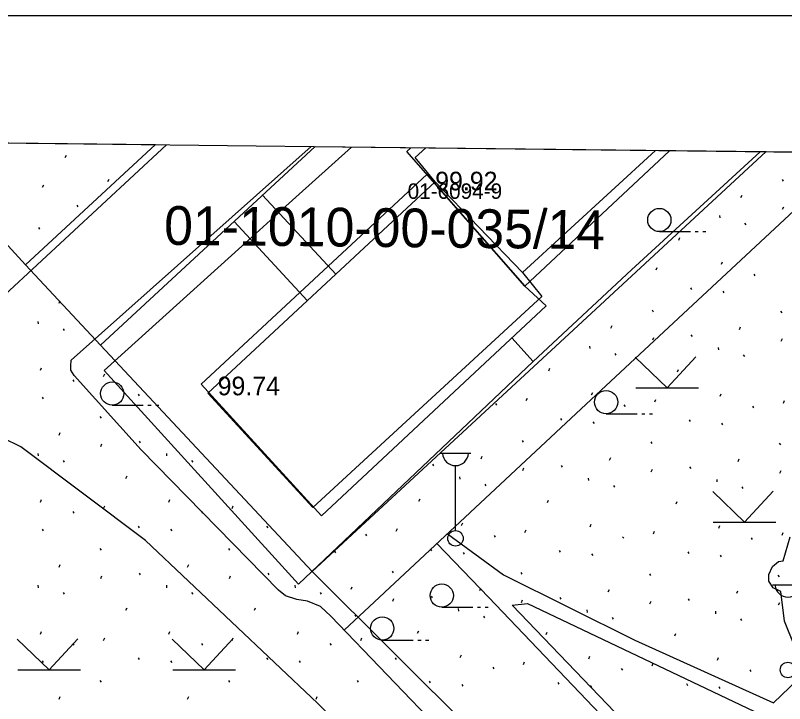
# Model space of a CAD drawing. Extents: x 412225 to 413380, y 4456471 to 4457189.
# Drawn here: x 412295.86 to 412345.47, y 4457144.55 to 4457188.94 of the extents above; entities that cross this region are included whole.
import ezdxf

# ---------------------------------------------------------------- set-up
doc = ezdxf.new("R2010")
doc.units = 0
for name, color, linetype in [('0_HALİHAZIR', 7, 'Continuous'), ('0_KADASTRO', 7, 'Continuous'), ('0_ÇERÇEVE', 7, 'Continuous'), ('Level 27', 7, 'Continuous'), ('Level 41', 7, 'Continuous'), ('Level 56', 7, 'Continuous'), ('Level 57', 7, 'Continuous'), ('Level 59', 7, 'Continuous')]:
    doc.layers.add(name, color=color, linetype=linetype)

msp = doc.modelspace()

# ---------------------------------------------------------------- linework, layer by layer
at = {"layer": '0_HALİHAZIR'}
for p, q in [((412337.395, 4457174.99), (412339.395, 4457174.99)), ((412339.695, 4457174.99), (412339.895, 4457174.99)), ((412340.195, 4457174.99), (412340.395, 4457174.99)), ((412337.894, 4457164.907), (412335.834, 4457166.897)), ((412337.894, 4457164.907), (412339.744, 4457166.917)), ((412335.874, 4457164.907), (412339.914, 4457164.907)), ((412302.11, 4457163.794), (412304.11, 4457163.794)), ((412304.41, 4457163.794), (412304.61, 4457163.794)), ((412304.91, 4457163.794), (412305.11, 4457163.794)), ((412333.958, 4457163.242), (412335.958, 4457163.242)), ((412336.258, 4457163.242), (412336.458, 4457163.242)), ((412336.758, 4457163.242), (412336.958, 4457163.242)), ((412323.246, 4457160.706), (412325.246, 4457160.706)), ((412324.246, 4457155.706), (412324.246, 4457159.899)), ((412342.894, 4457156.247), (412340.834, 4457158.237)), ((412342.894, 4457156.247), (412344.744, 4457158.258)), ((412340.874, 4457156.247), (412344.914, 4457156.248)), ((412344.689, 4457152.218), (412346.689, 4457152.218)), ((412323.362, 4457150.766), (412325.362, 4457150.766)), ((412325.662, 4457150.766), (412325.862, 4457150.766)), ((412326.162, 4457150.766), (412326.362, 4457150.766)), ((412298.036, 4457146.722), (412295.976, 4457148.712)), ((412298.036, 4457146.722), (412299.886, 4457148.732)), ((412308.036, 4457146.722), (412305.976, 4457148.712)), ((412308.036, 4457146.722), (412309.886, 4457148.732)), ((412319.523, 4457148.644), (412321.523, 4457148.645)), ((412321.823, 4457148.645), (412322.023, 4457148.645)), ((412322.323, 4457148.645), (412322.523, 4457148.645)), ((412296.016, 4457146.722), (412300.056, 4457146.722)), ((412306.016, 4457146.722), (412310.056, 4457146.722))]:
    msp.add_line(p, q, dxfattribs=at)
for points in [[(412284.733, 4457164.699), (412285.365, 4457164.43), (412286.294, 4457164.331), (412287.062, 4457164.426), (412287.813, 4457164.669), (412288.482, 4457165.003), (412288.892, 4457165.313), (412295.177, 4457170.909), (412305.604, 4457180.586)], [(412359.175, 4457112.345), (412356.387, 4457113.12), (412352.771, 4457114.27), (412350.826, 4457115.173), (412349.886, 4457115.776), (412342.089, 4457123.456), (412327.111, 4457138.846), (412316.211, 4457150.183), (412315.531, 4457150.81), (412314.7, 4457151.149), (412314.005, 4457151.259), (412313.293, 4457151.506), (412312.832, 4457151.862), (412303.976, 4457160.915), (412299.654, 4457165.706), (412299.427, 4457166.062), (412299.428, 4457166.32), (412299.461, 4457166.7), (412314.947, 4457180.477)], [(412312.682, 4457176.065), (412317.531, 4457180.447)], [(412338.055, 4457180.206), (412328.727, 4457171.476), (412321.106, 4457180.156), (412321.373, 4457180.402)], [(412343.904, 4457180.138), (412335.606, 4457172.533)], [(412317.067, 4457149.293), (412333.328, 4457164.459), (412347.336, 4457177.505), (412347.753, 4457177.483), (412348.105, 4457177.379), (412364.603, 4457159.572), (412379.131, 4457143.812), (412379.096, 4457143.617), (412379.04, 4457143.497), (412349.764, 4457115.897)], [(412311.123, 4457174.656), (412312.792, 4457176.164)], [(412329.254, 4457166.609), (412314.13, 4457152.244), (412301.577, 4457166.03), (412311.123, 4457174.656)], [(412335.606, 4457172.533), (412329.254, 4457166.609), (412327.871, 4457168.139)], [(412335.147, 4457124.46), (412315.339, 4457144.57), (412304.259, 4457155.068), (412296.215, 4457161.101), (412295.077, 4457161.666), (412294.576, 4457161.729), (412294.053, 4457161.609), (412293.255, 4457161.184), (412291.902, 4457160.235), (412291.075, 4457159.245), (412290.485, 4457158.329), (412290.192, 4457157.681), (412289.83, 4457156.409), (412289.781, 4457155.476), (412289.928, 4457154.313), (412290.377, 4457152.801), (412291.472, 4457150.013), (412295.556, 4457138.396)], [(412323.727, 4457155.505), (412327.338, 4457152.854), (412335.809, 4457148.631), (412344.759, 4457144.603), (412346.806, 4457146.561), (412345.468, 4457149.867), (412345.225, 4457151.786), (412344.732, 4457152.009), (412344.46, 4457152.441), (412344.459, 4457152.884), (412344.683, 4457153.401), (412345.081, 4457153.724), (412345.377, 4457153.746), (412345.841, 4457155.308)], [(412355.283, 4457121.1), (412339.005, 4457138.182), (412326.396, 4457151.393), (412323.051, 4457154.875)], [(412350.837, 4457126.999), (412327.897, 4457150.89), (412328.886, 4457150.997), (412344.387, 4457143.635), (412346.734, 4457138.715), (412350.828, 4457127.061)]]:
    msp.add_lwpolyline(points, dxfattribs=at)
msp.add_lwpolyline([(412328.727, 4457171.476), (412330.087, 4457170.211), (412315.597, 4457156.661), (412307.842, 4457165.151), (412322.402, 4457178.679)], close=True, dxfattribs=at)
for centre, radius in [((412337.395, 4457175.74), 0.75), ((412302.11, 4457164.544), 0.75), ((412333.958, 4457163.992), 0.75), ((412324.246, 4457155.206), 0.5), ((412323.362, 4457151.516), 0.75), ((412319.523, 4457149.394), 0.75), ((412345.689, 4457146.718), 0.5)]:
    msp.add_circle(centre, radius, dxfattribs=at)
for centre in [(412324.246, 4457160.736), (412345.689, 4457152.248)]:
    msp.add_arc(centre, 0.837, 183.298, 356.9072, dxfattribs=at)
at = {"layer": '0_KADASTRO'}
for points in [[(412255.662, 4457181.172), (412304.895, 4457180.603)], [(412304.895, 4457180.603), (412296.516, 4457172.853), (412301.357, 4457167.672), (412315.011, 4457153.058), (412331.864, 4457168.65), (412344.29, 4457180.147)], [(412344.29, 4457180.147), (412331.864, 4457168.65), (412315.011, 4457153.058), (412301.357, 4457167.672), (412315.204, 4457180.483)], [(412315.204, 4457180.483), (412344.29, 4457180.147)], [(412344.29, 4457180.147), (412351.343, 4457180.066)]]:
    msp.add_lwpolyline(points, dxfattribs=at)
at = {"layer": '0_ÇERÇEVE'}
for points in [[(412231.94, 4457188.937), (413313.937, 4457188.937), (413313.937, 4456471.176), (412231.94, 4456471.176)], [(412246.74, 4457181.275), (413310.435, 4457168.98), (413302.463, 4456474.947), (412238.67, 4456487.241)]]:
    msp.add_lwpolyline(points, close=True, dxfattribs=at)
at = {"layer": 'Level 27'}
msp.add_lwpolyline([(412304.895, 4457180.603), (412296.516, 4457172.853), (412301.357, 4457167.672), (412315.204, 4457180.483)], dxfattribs=at)
at = {"layer": 'Level 41'}
for p, q in [((412299.074, 4457179.772), (412299.148, 4457179.932)), ((412301.831, 4457178.214), (412301.902, 4457178.373)), ((412345.306, 4457178.359), (412345.376, 4457178.252)), ((412297.617, 4457177.849), (412297.689, 4457178.008)), ((412342.653, 4457177.193), (412342.726, 4457177.352)), ((412299.825, 4457176.689), (412299.895, 4457176.582)), ((412345.345, 4457176.437), (412345.418, 4457176.596)), ((412341.27, 4457176.032), (412341.287, 4457175.872)), ((412297.354, 4457175.262), (412297.424, 4457175.154)), ((412342.895, 4457175.546), (412342.964, 4457175.438)), ((412338.647, 4457174.445), (412338.721, 4457174.605)), ((412337.189, 4457172.522), (412337.262, 4457172.681)), ((412341.403, 4457172.887), (412341.475, 4457173.046)), ((412343.492, 4457172.25), (412343.562, 4457172.143)), ((412339.397, 4457171.362), (412339.467, 4457171.255)), ((412341.494, 4457171.149), (412341.564, 4457171.041)), ((412298.676, 4457170.374), (412298.738, 4457170.513)), ((412336.927, 4457169.935), (412336.997, 4457169.827)), ((412345.219, 4457169.85), (412345.289, 4457169.742)), ((412297.305, 4457169.199), (412297.323, 4457169.039)), ((412298.935, 4457168.729), (412299.005, 4457168.622)), ((412334.274, 4457168.769), (412334.346, 4457168.927)), ((412342.566, 4457168.684), (412342.639, 4457168.842)), ((412336.965, 4457168.012), (412337.039, 4457168.171)), ((412339.433, 4457168.332), (412339.503, 4457168.224)), ((412345.258, 4457167.927), (412345.331, 4457168.087)), ((412332.891, 4457167.608), (412332.907, 4457167.448)), ((412341.183, 4457167.523), (412341.2, 4457167.363)), ((412334.516, 4457167.121), (412334.585, 4457167.013)), ((412342.808, 4457167.036), (412342.877, 4457166.929)), ((412297.47, 4457166.055), (412297.54, 4457166.215)), ((412330.267, 4457166.021), (412330.341, 4457166.18)), ((412301.553, 4457165.647), (412301.624, 4457165.807)), ((412338.56, 4457165.936), (412338.633, 4457166.095)), ((412299.565, 4457165.439), (412299.636, 4457165.333)), ((412297.579, 4457164.318), (412297.65, 4457164.211)), ((412303.773, 4457164.51), (412303.844, 4457164.403)), ((412328.81, 4457164.097), (412328.882, 4457164.257)), ((412333.023, 4457164.462), (412333.095, 4457164.622)), ((412337.102, 4457164.013), (412337.175, 4457164.172)), ((412341.316, 4457164.377), (412341.388, 4457164.537)), ((412326.819, 4457163.91), (412326.889, 4457163.803)), ((412335.112, 4457163.825), (412335.182, 4457163.718)), ((412343.405, 4457163.74), (412343.475, 4457163.633)), ((412345.395, 4457163.928), (412345.467, 4457164.087)), ((412301.317, 4457163.057), (412301.388, 4457162.95)), ((412331.018, 4457162.938), (412331.088, 4457162.83)), ((412333.115, 4457162.724), (412333.185, 4457162.617)), ((412339.31, 4457162.853), (412339.38, 4457162.745)), ((412341.407, 4457162.639), (412341.477, 4457162.532)), ((412298.676, 4457161.864), (412298.747, 4457162.023)), ((412301.375, 4457161.135), (412301.447, 4457161.295)), ((412303.84, 4457161.48), (412303.911, 4457161.373)), ((412328.547, 4457161.51), (412328.617, 4457161.402)), ((412336.84, 4457161.425), (412336.909, 4457161.317)), ((412345.132, 4457161.34), (412345.202, 4457161.232)), ((412297.305, 4457160.689), (412297.323, 4457160.529)), ((412298.935, 4457160.219), (412299.005, 4457160.112)), ((412305.598, 4457160.689), (412305.616, 4457160.529)), ((412307.228, 4457160.219), (412307.298, 4457160.112)), ((412325.894, 4457160.344), (412325.967, 4457160.502)), ((412334.187, 4457160.259), (412334.259, 4457160.417)), ((412342.479, 4457160.174), (412342.552, 4457160.333)), ((412322.761, 4457159.992), (412322.831, 4457159.884)), ((412328.585, 4457159.587), (412328.659, 4457159.747)), ((412331.054, 4457159.907), (412331.124, 4457159.799)), ((412339.346, 4457159.822), (412339.416, 4457159.715)), ((412302.991, 4457159.075), (412303.063, 4457159.235)), ((412336.878, 4457159.503), (412336.952, 4457159.662)), ((412345.17, 4457159.418), (412345.244, 4457159.577)), ((412324.511, 4457159.183), (412324.527, 4457159.023)), ((412332.804, 4457159.098), (412332.82, 4457158.938)), ((412341.096, 4457159.013), (412341.112, 4457158.853)), ((412326.136, 4457158.696), (412326.205, 4457158.589)), ((412334.429, 4457158.612), (412334.498, 4457158.504)), ((412342.721, 4457158.527), (412342.79, 4457158.419)), ((412321.888, 4457157.596), (412321.961, 4457157.755)), ((412297.47, 4457157.545), (412297.54, 4457157.705)), ((412301.553, 4457157.137), (412301.624, 4457157.297)), ((412305.763, 4457157.545), (412305.833, 4457157.705)), ((412309.846, 4457157.137), (412309.917, 4457157.297)), ((412330.18, 4457157.511), (412330.254, 4457157.67)), ((412338.473, 4457157.426), (412338.546, 4457157.585)), ((412299.565, 4457156.929), (412299.636, 4457156.823)), ((412307.858, 4457156.929), (412307.929, 4457156.823)), ((412297.579, 4457155.808), (412297.65, 4457155.701)), ((412303.773, 4457156), (412303.844, 4457155.893)), ((412305.872, 4457155.808), (412305.943, 4457155.701)), ((412312.066, 4457156), (412312.137, 4457155.893)), ((412320.43, 4457155.673), (412320.502, 4457155.832)), ((412324.644, 4457156.038), (412324.715, 4457156.197)), ((412328.722, 4457155.588), (412328.795, 4457155.747)), ((412332.936, 4457155.953), (412333.008, 4457156.112)), ((412341.229, 4457155.868), (412341.301, 4457156.027)), ((412318.44, 4457155.485), (412318.51, 4457155.378)), ((412326.732, 4457155.4), (412326.802, 4457155.293)), ((412335.025, 4457155.315), (412335.095, 4457155.209)), ((412337.015, 4457155.503), (412337.088, 4457155.662)), ((412345.308, 4457155.418), (412345.38, 4457155.577)), ((412343.318, 4457155.23), (412343.387, 4457155.124)), ((412301.317, 4457154.547), (412301.388, 4457154.44)), ((412309.61, 4457154.547), (412309.681, 4457154.44)), ((412316.443, 4457154.383), (412316.512, 4457154.277)), ((412322.638, 4457154.513), (412322.708, 4457154.405)), ((412324.735, 4457154.3), (412324.805, 4457154.192)), ((412330.931, 4457154.428), (412331.001, 4457154.32)), ((412339.223, 4457154.343), (412339.293, 4457154.236)), ((412333.028, 4457154.215), (412333.097, 4457154.107)), ((412341.32, 4457154.13), (412341.39, 4457154.022)), ((412298.676, 4457153.354), (412298.747, 4457153.513)), ((412306.969, 4457153.354), (412307.04, 4457153.513)), ((412301.375, 4457152.625), (412301.447, 4457152.785)), ((412303.84, 4457152.97), (412303.911, 4457152.863)), ((412309.668, 4457152.625), (412309.74, 4457152.785)), ((412312.133, 4457152.97), (412312.204, 4457152.863)), ((412320.167, 4457153.085), (412320.237, 4457152.978)), ((412328.46, 4457153), (412328.53, 4457152.893)), ((412336.752, 4457152.916), (412336.822, 4457152.808)), ((412345.045, 4457152.831), (412345.115, 4457152.723)), ((412297.305, 4457152.179), (412297.323, 4457152.019)), ((412305.598, 4457152.179), (412305.616, 4457152.019)), ((412313.891, 4457152.179), (412313.909, 4457152.019)), ((412317.514, 4457151.919), (412317.587, 4457152.078)), ((412325.807, 4457151.834), (412325.879, 4457151.993)), ((412334.099, 4457151.75), (412334.172, 4457151.908)), ((412342.392, 4457151.665), (412342.465, 4457151.823)), ((412298.935, 4457151.709), (412299.005, 4457151.602)), ((412307.228, 4457151.709), (412307.298, 4457151.602)), ((412315.521, 4457151.709), (412315.591, 4457151.602)), ((412320.206, 4457151.163), (412320.279, 4457151.322)), ((412322.674, 4457151.483), (412322.744, 4457151.375)), ((412330.967, 4457151.398), (412331.037, 4457151.29)), ((412339.259, 4457151.313), (412339.329, 4457151.205)), ((412328.498, 4457151.078), (412328.572, 4457151.237)), ((412336.791, 4457150.993), (412336.864, 4457151.152)), ((412345.083, 4457150.908), (412345.157, 4457151.067)), ((412302.991, 4457150.565), (412303.063, 4457150.725)), ((412311.284, 4457150.565), (412311.356, 4457150.725)), ((412324.424, 4457150.674), (412324.44, 4457150.513)), ((412332.716, 4457150.589), (412332.733, 4457150.429)), ((412341.009, 4457150.504), (412341.025, 4457150.344)), ((412317.756, 4457150.272), (412317.825, 4457150.164)), ((412326.049, 4457150.187), (412326.118, 4457150.079)), ((412334.342, 4457150.102), (412334.41, 4457149.994)), ((412342.634, 4457150.017), (412342.703, 4457149.909)), ((412297.47, 4457149.035), (412297.54, 4457149.195)), ((412305.763, 4457149.035), (412305.833, 4457149.195)), ((412314.056, 4457149.035), (412314.126, 4457149.195)), ((412321.801, 4457149.086), (412321.874, 4457149.246)), ((412330.093, 4457149.001), (412330.167, 4457149.161)), ((412338.386, 4457148.917), (412338.459, 4457149.076)), ((412299.565, 4457148.419), (412299.636, 4457148.313)), ((412301.553, 4457148.627), (412301.624, 4457148.787)), ((412307.858, 4457148.419), (412307.929, 4457148.313)), ((412309.846, 4457148.627), (412309.917, 4457148.787)), ((412316.151, 4457148.419), (412316.222, 4457148.313)), ((412318.139, 4457148.627), (412318.21, 4457148.787)), ((412303.773, 4457147.49), (412303.844, 4457147.383)), ((412312.066, 4457147.49), (412312.137, 4457147.383)), ((412320.359, 4457147.49), (412320.43, 4457147.383)), ((412324.557, 4457147.528), (412324.628, 4457147.687)), ((412332.849, 4457147.443), (412332.921, 4457147.602)), ((412341.142, 4457147.358), (412341.213, 4457147.518)), ((412297.579, 4457147.298), (412297.65, 4457147.191)), ((412305.872, 4457147.298), (412305.943, 4457147.191)), ((412314.165, 4457147.298), (412314.236, 4457147.191)), ((412326.645, 4457146.891), (412326.715, 4457146.784)), ((412328.635, 4457147.078), (412328.708, 4457147.238)), ((412334.938, 4457146.806), (412335.008, 4457146.699)), ((412336.928, 4457146.993), (412337.001, 4457147.153)), ((412345.22, 4457146.909), (412345.293, 4457147.068)), ((412343.23, 4457146.721), (412343.3, 4457146.614)), ((412301.317, 4457146.037), (412301.388, 4457145.93)), ((412309.61, 4457146.037), (412309.681, 4457145.93)), ((412317.903, 4457146.037), (412317.974, 4457145.93)), ((412322.551, 4457146.003), (412322.621, 4457145.896)), ((412330.844, 4457145.919), (412330.913, 4457145.811)), ((412339.136, 4457145.834), (412339.206, 4457145.726)), ((412324.648, 4457145.79), (412324.718, 4457145.682)), ((412332.94, 4457145.705), (412333.01, 4457145.597)), ((412341.233, 4457145.62), (412341.303, 4457145.513)), ((412298.676, 4457144.844), (412298.747, 4457145.003)), ((412306.969, 4457144.844), (412307.04, 4457145.003)), ((412315.262, 4457144.844), (412315.333, 4457145.003))]:
    msp.add_line(p, q, dxfattribs=at)
at = {"layer": 'Level 57'}
msp.add_line((412296.516, 4457172.853), (412289.176, 4457180.784), dxfattribs=at)
for points in [[(412344.29, 4457180.147), (412331.864, 4457168.65), (412315.011, 4457153.058), (412301.357, 4457167.672)], [(412315.011, 4457153.058), (412367.356, 4457100.937), (412369.613, 4457103.012)]]:
    msp.add_lwpolyline(points, dxfattribs=at)
at = {"layer": 'Level 59'}
for p, q in [((412316.52, 4457172.243), (412311.805, 4457177.339)), ((412314.689, 4457170.542), (412309.97, 4457175.642))]:
    msp.add_line(p, q, dxfattribs=at)
for points in [[(412322.936, 4457178.209), (412321.641, 4457179.766), (412322.333, 4457180.401)], [(412337.155, 4457180.23), (412328.566, 4457172.353)]]:
    msp.add_lwpolyline(points, dxfattribs=at)
msp.add_lwpolyline([(412315.042, 4457157.2), (412308.273, 4457164.576), (412322.936, 4457178.209), (412328.566, 4457172.353), (412329.806, 4457170.795)], close=True, dxfattribs=at)

# ---------------------------------------------------------------- texts
at = {"layer": '0_HALİHAZIR'}
for s, p in [('99.92', (412322.939, 4457177.652)), ('99.74', (412308.908, 4457164.434))]:
    msp.add_text(s, height=1.2, dxfattribs=at).set_placement(p)
at = {"layer": '0_KADASTRO'}
msp.add_text('01-6094-9', height=1, dxfattribs=at).set_placement((412321.159, 4457177.102))
msp.add_text('01-6094-9', height=1, dxfattribs=at).set_placement((412321.159, 4457177.102))
at = {"layer": 'Level 56'}
msp.add_text('01-1010-00-035/14', height=2.5, rotation=359.4136, dxfattribs=at).set_placement((412305.444, 4457174.144))

doc.saveas('drawing.dxf')
